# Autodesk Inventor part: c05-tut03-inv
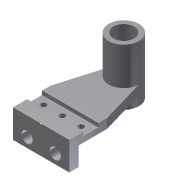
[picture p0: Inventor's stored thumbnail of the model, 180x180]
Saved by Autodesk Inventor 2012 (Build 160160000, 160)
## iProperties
Created: 2010-02
Part Number: c05-tut03-inv
Document SubType Name: Modeling
Designer: CADSoft
Density: 1 g/cm^3
Material: Default
Author: CADSoft
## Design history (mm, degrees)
sketch "Sketch1"
  geometry: 1 further point
sketch "Sketch2"
  geometry: L1 (40, 0)-(40, -10); L2 (10, -30)-(0, -30); L3 (0, -30)-(0, 0); L4 (31, 0)-(31, -4); L5 (31, -4)-(15, -4); L6 (15, -4)-(15, 0); L7 (40, -10)-(10, -10); L8 (10, -10)-(10, -30); L9 (0, 0)-(15, 0); L10 (31, 0)-(40, 0)
  constraints: 20 end point, 1 collinear, 1 horizontal, 1 perpendicular
  dimensions: "d0" = 4 distance of L5.end L6.end; "d1" = 30 distance of L2.end L3.end; "d2" = 15 distance of L3.end L6.end; "d3" = 10 distance of L2.start L2.end; "d4" = 40 distance between parallel lines of L1 L3; "d5" = 16 distance of L4.end L5.end
extrude "Extrusion1" new body sketch "Sketch2" stored distance "d6" = 60; taper "d7" = 0 deg
sketch "Sketch3"
  geometry: L1 (0, 0)-(60, 0) reference; L2 (0, 0)-(14, 48); L3 (14, 48)-(46, 48); L4 (46, 48)-(60, 0); 1 further point
  constraints: 6 end point, 1 equal length
  dimensions: "d8" = 48 distance between parallel lines of L3 L1; "d9" = 32 distance of L2.end L3.end
extrude "Extrusion2" join sketch "Sketch3" distance "d10" = 10; taper "d11" = 0 deg
workplane "Work Plane1"
sketch "Sketch4"
  geometry: L1 (0, 30)-(0, 0) reference; L2 (14, 78)-(46, 78) reference; C1 r 16 at (30, 78); 1 further point
  constraints: 1 centre point, 1 midpoint
  dimensions: "d14" = 32 diameter of C1; "d15" = 30 distance from line of C1.centre L1
extrude "Extrusion3" join sketch "Sketch4" distance "d16" = 60; taper "d17" = 0 deg
sketch "Sketch5"
  geometry: L1 (60, -30)-(60, 0) reference; L2 (0, -30)-(60, -30) reference; C1 r 6 at (15, -20); C2 r 6 at (45, -20); 1 further point
  constraints: 2 centre point, 1 equal radius, 1 horizontal alignment
  dimensions: "d18" = 10 distance from line of L2 C1.centre; "d19" = 30 distance of C2.centre C1.centre; "d20" = 15 distance from line of L1 C2.centre; "d21" = 12 diameter of C1
extrude "Extrusion4" cut sketch "Sketch5" stored distance "d22" = 60; taper "d23" = 0 deg
sketch "Sketch6"
  geometry: L1 (60, -31)-(0, -31) reference; L2 (0, -16)-(0, -31) reference; C1 r 3 at (30, -8.5); C2 r 3 at (10, -8.5); C3 r 3 at (50, -8.5); 1 further point
  constraints: 3 centre point, 2 equal radius, 2 horizontal alignment
  dimensions: "d24" = 6 diameter of C2; "d25" = 22.5 distance from line of L1 C2.centre; "d26" = 10 distance from line of L2 C2.centre; "d27" = 20 distance of C1.centre C2.centre; "d28" = 20 distance of C3.centre C1.centre
extrude "Extrusion5" cut sketch "Sketch6" stored distance "d29" = 60; taper "d30" = 0 deg
sketch "Sketch7"
  geometry: C1 r 16 at (0, 0) reference; C2 r 11 at (0, 0); 1 further point
  constraints: 1 centre point, 1 coincident
  dimensions: "d31" = 22 diameter of C2
extrude "Extrusion6" cut sketch "Sketch7" stored distance "d32" = 60; taper "d33" = 0 deg
body "Solid1"
